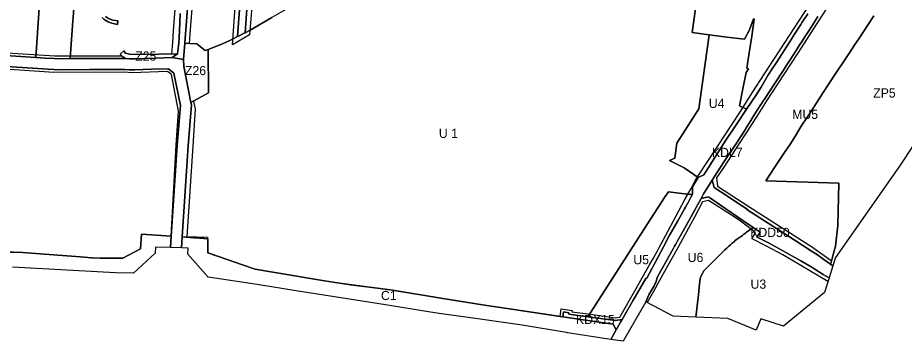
# Model space of a CAD drawing. Extents: x 7428841 to 7433518, y 5545054 to 5546840.
# Drawn here: x 7431956 to 7432924, y 5545054 to 5545407 of the extents above; entities that cross this region are included whole.
import ezdxf

# ---------------------------------------------------------------- set-up
doc = ezdxf.new("R2010")
doc.units = 0
for name, color, linetype in [('linie_rozgraniczajace', 7, 'Continuous'), ('linie_zabudowy_nieprzekraczalne', 7, 'Continuous'), ('oznaczenia_przeznaczen', 7, 'Continuous')]:
    doc.layers.add(name, color=color, linetype=linetype)

msp = doc.modelspace()

# ---------------------------------------------------------------- linework, layer by layer
at = {"layer": 'linie_rozgraniczajace'}
for points in [[(7432196.1, 5545386.25), (7432202.71, 5545474.72), (7432206.08, 5545525.88), (7432208.81, 5545561.69), (7432203.6, 5545569.04), (7432210.29, 5545567.85), (7432216.33, 5545566.52), (7432223.28, 5545565.18), (7432216.71, 5545560.01), (7432214.06, 5545525.32), (7432212.38, 5545499.74), (7432210.69, 5545474.16), (7432207.56, 5545432.32), (7432204.44, 5545390.47), (7432203.54, 5545390.02), (7432197.14, 5545386.77)], [(7432204.44, 5545390.47), (7432207.56, 5545432.32), (7432210.69, 5545474.16), (7432212.38, 5545499.74), (7432214.06, 5545525.32), (7432216.71, 5545560.01), (7432223.28, 5545565.18), (7432244.58, 5545561.06), (7432283.54, 5545552.91), (7432290.42, 5545551.44), (7432291.32, 5545550.69), (7432296.95, 5545543.74), (7432296.3, 5545532.35), (7432295.25, 5545513.02), (7432294.01, 5545489.23), (7432293.34, 5545476.24), (7432291.3, 5545440.58), (7432274.26, 5545430.67), (7432233.45, 5545406.94), (7432209.79, 5545393.18)], [(7432667.52, 5545251.05), (7432673.15, 5545253.66), (7432675.27, 5545270.1), (7432699.59, 5545307.32), (7432710.72, 5545388.26), (7432729.95, 5545385.76), (7432749.18, 5545383.25), (7432754.57, 5545393.55), (7432759.06, 5545405.63), (7432759.96, 5545405.26), (7432757.16, 5545386.62), (7432754.42, 5545368.61), (7432751.84, 5545351.8), (7432753.62, 5545351.19), (7432750.92, 5545347.04), (7432747.88, 5545331.2), (7432743.92, 5545310.59), (7432751.27, 5545307.07), (7432740.14, 5545290.19), (7432729, 5545273.31), (7432704.97, 5545235.65), (7432698.55, 5545232.67), (7432689.21, 5545239.02), (7432683.27, 5545243.05)], [(7432067.99, 5545367.17), (7432072.24, 5545370.55), (7432074.07, 5545368.16), (7432078.32, 5545367.09), (7432089.62, 5545366.59), (7432110.15, 5545367.09), (7432130.68, 5545367.58), (7432125.02, 5545363.36), (7432106.88, 5545362.74), (7432083.68, 5545361.95), (7432078.49, 5545361.82), (7432073.98, 5545362.3), (7432071.11, 5545363.99)], [(7432137.2, 5545361.26), (7432138.7, 5545378.94), (7432143.99, 5545378.66), (7432151.8, 5545378.26), (7432160.95, 5545371.14), (7432163.99, 5545372.31), (7432164.46, 5545325.04), (7432145.38, 5545314.39), (7432137.63, 5545353.68)], [(7432701.88, 5545209.84), (7432704.68, 5545214.94), (7432707.84, 5545219.89), (7432710.99, 5545224.83), (7432714.12, 5545229.84), (7432714.13, 5545229.81), (7432716.08, 5545221.55), (7432731.85, 5545211.37), (7432741.98, 5545204.74), (7432752.11, 5545198.11), (7432751.92, 5545197.81), (7432803.36, 5545164.61), (7432822.42, 5545152.36), (7432828.77, 5545148.28), (7432835.85, 5545143.22), (7432842.93, 5545138.16), (7432845.64, 5545136.22), (7432841.47, 5545123.06), (7432837.72, 5545125.39), (7432835.19, 5545126.96), (7432821.88, 5545135.06), (7432810.56, 5545141.82), (7432794.5, 5545150.78), (7432786.64, 5545155.11), (7432778.78, 5545159.44), (7432775.28, 5545161.37), (7432771.78, 5545163.29), (7432763.89, 5545167.27), (7432762.82, 5545167.63), (7432766.45, 5545172.84), (7432758.66, 5545178.14), (7432747.51, 5545185.75), (7432722.99, 5545202.46), (7432710.96, 5545210.66), (7432709.63, 5545211.57)], [(7432578.18, 5545080.77), (7432642.84, 5545180.91), (7432662.74, 5545211.71), (7432666.18, 5545217.04), (7432689.64, 5545214.06), (7432692.67, 5545214.56), (7432690.37, 5545210.45), (7432687.65, 5545205.38), (7432684.92, 5545200.31), (7432683.84, 5545198.41), (7432680.11, 5545191.89), (7432676.38, 5545185.38), (7432667.04, 5545168.88), (7432660.91, 5545157.16), (7432654.78, 5545145.45), (7432642.58, 5545122.98), (7432641.73, 5545122.61), (7432627.38, 5545098.18), (7432620.55, 5545085.97), (7432615.62, 5545077.57), (7432615.6, 5545077.57), (7432608.55, 5545076.48)], [(7432641.43, 5545096.89), (7432644.83, 5545104.52), (7432648.35, 5545110.71), (7432649.44, 5545112.59), (7432650.53, 5545114.48), (7432651.51, 5545116.26), (7432652.48, 5545118.04), (7432653.05, 5545119.59), (7432654.5, 5545124.17), (7432671.87, 5545155.36), (7432673.03, 5545157.66), (7432674.18, 5545159.95), (7432675.78, 5545162.8), (7432680.53, 5545171.2), (7432685.28, 5545179.6), (7432701.88, 5545209.84), (7432709.63, 5545211.57), (7432710.96, 5545210.66), (7432722.99, 5545202.46), (7432747.51, 5545185.75), (7432758.66, 5545178.14), (7432755.12, 5545175.61), (7432751.57, 5545173.08), (7432750.29, 5545172.03), (7432748.61, 5545170.72), (7432746.93, 5545169.41), (7432743.8, 5545167.12), (7432740.66, 5545164.83), (7432739.24, 5545163.72), (7432737.82, 5545162.61), (7432736.82, 5545161.77), (7432735.83, 5545160.92), (7432733.92, 5545159.23), (7432732.01, 5545157.53), (7432729.98, 5545155.69), (7432727.96, 5545153.85), (7432716.58, 5545142.62), (7432711.01, 5545137.03), (7432707.3, 5545133.23), (7432705.99, 5545131.91), (7432705.1, 5545131.18), (7432704.58, 5545130.49), (7432703.99, 5545129.52), (7432703.61, 5545128.75), (7432702.34, 5545126.11), (7432701.71, 5545124.61), (7432701.08, 5545123.35), (7432700.7, 5545122.73), (7432699.7, 5545112.9), (7432698.88, 5545104.78), (7432696.27, 5545080.44), (7432671.24, 5545081.55)], [(7432696.27, 5545080.44), (7432698.88, 5545104.78), (7432699.7, 5545112.9), (7432700.7, 5545122.73), (7432701.08, 5545123.35), (7432701.71, 5545124.61), (7432702.34, 5545126.11), (7432703.61, 5545128.75), (7432703.99, 5545129.52), (7432704.58, 5545130.49), (7432705.1, 5545131.18), (7432705.99, 5545131.91), (7432707.3, 5545133.23), (7432711.01, 5545137.03), (7432716.58, 5545142.62), (7432727.96, 5545153.85), (7432729.98, 5545155.69), (7432732.01, 5545157.53), (7432733.92, 5545159.23), (7432735.83, 5545160.92), (7432736.82, 5545161.77), (7432737.82, 5545162.61), (7432739.24, 5545163.72), (7432740.66, 5545164.83), (7432743.8, 5545167.12), (7432746.93, 5545169.41), (7432748.61, 5545170.72), (7432750.29, 5545172.03), (7432751.57, 5545173.08), (7432755.12, 5545175.61), (7432758.66, 5545178.14), (7432766.45, 5545172.84), (7432762.82, 5545167.63), (7432763.89, 5545167.27), (7432771.78, 5545163.29), (7432775.28, 5545161.37), (7432778.78, 5545159.44), (7432786.64, 5545155.11), (7432794.5, 5545150.78), (7432810.56, 5545141.82), (7432821.88, 5545135.06), (7432835.19, 5545126.96), (7432837.72, 5545125.39), (7432841.47, 5545123.06), (7432836.5, 5545107.35), (7432791.84, 5545070.54), (7432767.08, 5545078.44), (7432762.15, 5545066.15), (7432731.09, 5545078.89)], [(7432135.09, 5545155.79), (7432135.85, 5545167.75), (7432147.96, 5545166.94), (7432150.43, 5545166.77), (7432163.92, 5545165.87), (7432163.78, 5545150.44), (7432168.06, 5545148.95), (7432200.53, 5545137.62), (7432215.26, 5545132.49), (7432234.5, 5545129.24), (7432291.14, 5545119.99), (7432319.41, 5545115.67), (7432351.95, 5545111.58), (7432365.27, 5545109.89), (7432418.01, 5545101.07), (7432465.59, 5545093.37), (7432490.19, 5545089.57), (7432551.02, 5545080.69), (7432575.82, 5545077.12), (7432605.99, 5545072.61), (7432609.19, 5545066.4), (7432603.31, 5545056.07), (7432598.84, 5545056.76), (7432556.31, 5545063.34), (7432554.98, 5545063.55), (7432506.7, 5545071.44), (7432458.27, 5545078.49), (7432418.71, 5545083.98), (7432406.79, 5545085.63), (7432357.6, 5545093.7), (7432313.43, 5545100.66), (7432262.24, 5545108.71), (7432217.51, 5545115.83), (7432164.31, 5545124.04), (7432142.08, 5545149.06), (7432142.46, 5545155.57)], [(7432551.02, 5545080.69), (7432551.77, 5545086.01), (7432557.71, 5545085.17), (7432557.5, 5545083.69), (7432578.18, 5545080.77), (7432608.55, 5545076.48), (7432615.6, 5545077.57), (7432615.62, 5545077.57), (7432614.49, 5545075.65), (7432612.07, 5545071.62), (7432609.19, 5545066.4), (7432605.99, 5545072.61), (7432575.82, 5545077.12)]]:
    msp.add_lwpolyline(points, close=True, dxfattribs=at)
for points in [[(7431954.01, 5545558.44), (7431956.9, 5545558.72), (7431969.76, 5545559.94), (7431989.12, 5545562.68), (7431986.99, 5545527.39), (7431986.16, 5545515.18), (7431985.24, 5545502.71), (7431966.86, 5545502.19), (7431965.95, 5545492.23), (7431972.63, 5545491.63), (7431979.3, 5545491.02), (7431984.45, 5545490.31), (7431984.46, 5545490.31), (7431981.09, 5545438.88), (7431976.25, 5545363.59), (7431916.07, 5545367.52)], [(7432202.71, 5545474.72), (7432196.1, 5545386.25), (7432190.08, 5545383.2), (7432183.03, 5545379.63), (7432177.88, 5545377.65), (7432163.99, 5545372.31), (7432160.95, 5545371.14), (7432151.8, 5545378.26), (7432143.99, 5545378.66), (7432138.7, 5545378.94), (7432138.74, 5545379.48), (7432142.98, 5545436.66)], [(7432018.14, 5545426.1), (7432016.2, 5545398.51), (7432013.75, 5545362.17), (7432001.79, 5545362.09), (7431996.2, 5545362.19), (7431986.22, 5545362.87), (7431976.25, 5545363.59), (7431981.09, 5545438.88)], [(7432142.98, 5545436.66), (7432138.74, 5545379.48), (7432138.7, 5545378.94), (7432137.2, 5545361.26), (7432125.02, 5545363.36), (7432130.68, 5545367.58), (7432132.02, 5545379.09), (7432132.5, 5545385.71), (7432132.99, 5545392.34), (7432133.27, 5545401.81), (7432133.55, 5545411.29)], [(7432133.55, 5545411.29), (7432133.27, 5545401.81), (7432132.99, 5545392.34), (7432132.5, 5545385.71), (7432132.02, 5545379.09), (7432130.68, 5545367.58), (7432110.15, 5545367.09), (7432089.62, 5545366.59), (7432078.32, 5545367.09), (7432074.07, 5545368.16), (7432072.24, 5545370.55), (7432067.99, 5545367.17), (7432071.11, 5545363.99), (7432073.98, 5545362.3), (7432035.09, 5545362.25), (7432013.75, 5545362.17), (7432016.2, 5545398.51), (7432018.14, 5545426.1)], [(7432697.15, 5545427.52), (7432691.97, 5545390.71), (7432710.72, 5545388.26), (7432699.59, 5545307.32), (7432675.27, 5545270.1), (7432673.15, 5545253.66), (7432667.52, 5545251.05), (7432683.27, 5545243.05), (7432689.21, 5545239.02), (7432698.55, 5545232.67), (7432692.35, 5545222.48), (7432692.67, 5545214.56), (7432689.64, 5545214.06), (7432666.18, 5545217.04), (7432662.74, 5545211.71), (7432642.84, 5545180.91), (7432578.18, 5545080.77), (7432557.5, 5545083.69), (7432557.71, 5545085.17), (7432551.77, 5545086.01), (7432551.02, 5545080.69), (7432490.19, 5545089.57), (7432465.59, 5545093.37), (7432418.01, 5545101.07), (7432365.27, 5545109.89), (7432351.95, 5545111.58), (7432319.41, 5545115.67), (7432291.14, 5545119.99), (7432234.5, 5545129.24), (7432215.26, 5545132.49), (7432200.53, 5545137.62), (7432168.06, 5545148.95), (7432163.78, 5545150.44), (7432163.92, 5545165.87), (7432150.43, 5545166.77), (7432147.96, 5545166.94), (7432135.85, 5545167.75), (7432142.17, 5545267.1), (7432144.02, 5545289.51), (7432145.86, 5545311.93), (7432145.38, 5545314.39), (7432164.46, 5545325.04), (7432163.99, 5545372.31), (7432177.88, 5545377.65), (7432183.03, 5545379.63), (7432190.08, 5545383.2), (7432196.1, 5545386.25), (7432197.14, 5545386.77), (7432203.54, 5545390.02), (7432204.44, 5545390.47), (7432209.79, 5545393.18), (7432233.45, 5545406.94)], [(7432818.19, 5545411.13), (7432812.33, 5545402.01), (7432810.68, 5545399.44), (7432803.17, 5545387.74), (7432800.95, 5545384.33), (7432792.46, 5545371.24), (7432783.97, 5545358.15), (7432779.34, 5545351.02), (7432774.71, 5545343.9), (7432767.45, 5545330.92), (7432761.49, 5545322.12), (7432751.27, 5545307.07), (7432743.92, 5545310.59), (7432747.88, 5545331.2), (7432750.92, 5545347.04), (7432753.62, 5545351.19), (7432751.84, 5545351.8), (7432754.42, 5545368.61), (7432757.16, 5545386.62), (7432759.96, 5545405.26), (7432759.06, 5545405.63), (7432754.57, 5545393.55), (7432749.18, 5545383.25), (7432729.95, 5545385.76), (7432710.72, 5545388.26), (7432691.97, 5545390.71), (7432697.15, 5545427.52)], [(7432829.4, 5545407.97), (7432823.32, 5545398.63), (7432819.27, 5545392.39), (7432815.21, 5545386.15), (7432812.08, 5545381.38), (7432808.94, 5545376.61), (7432805.55, 5545371.01), (7432802.27, 5545365.98), (7432799, 5545360.94), (7432796.85, 5545357.6), (7432794.71, 5545354.26), (7432791.87, 5545349.49), (7432782.83, 5545335.83), (7432775.7, 5545325.12), (7432771.72, 5545319.06), (7432769.37, 5545315.49), (7432768.28, 5545313.77), (7432767.18, 5545312.06), (7432760.67, 5545301.85), (7432756.29, 5545294.73), (7432751.79, 5545287.83), (7432749.06, 5545283.37), (7432740.66, 5545270.01), (7432726.97, 5545250.16), (7432722.97, 5545243.88), (7432718.97, 5545237.6), (7432714.12, 5545229.84), (7432710.99, 5545224.83), (7432707.84, 5545219.89), (7432704.68, 5545214.94), (7432701.88, 5545209.84), (7432685.28, 5545179.6), (7432680.53, 5545171.2), (7432675.78, 5545162.8), (7432674.18, 5545159.95), (7432673.03, 5545157.66), (7432671.87, 5545155.36), (7432654.5, 5545124.17), (7432653.05, 5545119.59), (7432652.48, 5545118.04), (7432651.51, 5545116.26), (7432650.53, 5545114.48), (7432649.44, 5545112.59), (7432648.35, 5545110.71), (7432644.83, 5545104.52), (7432641.43, 5545096.89), (7432618.28, 5545056.6), (7432616.79, 5545054.01), (7432603.31, 5545056.07), (7432609.19, 5545066.4), (7432612.07, 5545071.62), (7432614.49, 5545075.65), (7432615.62, 5545077.57), (7432620.55, 5545085.97), (7432627.38, 5545098.18), (7432641.73, 5545122.61), (7432642.58, 5545122.98), (7432654.78, 5545145.45), (7432660.91, 5545157.16), (7432667.04, 5545168.88), (7432676.38, 5545185.38), (7432680.11, 5545191.89), (7432683.84, 5545198.41), (7432684.92, 5545200.31), (7432687.65, 5545205.38), (7432690.37, 5545210.45), (7432692.67, 5545214.56), (7432692.35, 5545222.48), (7432698.55, 5545232.67), (7432704.97, 5545235.65), (7432729, 5545273.31), (7432740.14, 5545290.19), (7432751.27, 5545307.07), (7432761.49, 5545322.12), (7432767.45, 5545330.92), (7432774.71, 5545343.9), (7432779.34, 5545351.02), (7432783.97, 5545358.15), (7432792.46, 5545371.24), (7432800.95, 5545384.33), (7432803.17, 5545387.74), (7432810.68, 5545399.44), (7432812.33, 5545402.01), (7432818.19, 5545411.13)], [(7432048.59, 5545407.18), (7432050.46, 5545405.31), (7432052.41, 5545403.84), (7432053.08, 5545403.42), (7432055.07, 5545402.41), (7432057.51, 5545401.2), (7432062.08, 5545400.03), (7432065.23, 5545399.37), (7432065.69, 5545403.42), (7432060.01, 5545404.05), (7432055.4, 5545405.97), (7432052.26, 5545408.11)], [(7432052.26, 5545408.11), (7432055.4, 5545405.97), (7432060.01, 5545404.05), (7432065.69, 5545403.42), (7432065.23, 5545399.37), (7432062.08, 5545400.03), (7432057.51, 5545401.2), (7432055.07, 5545402.41), (7432053.08, 5545403.42), (7432052.41, 5545403.84), (7432050.46, 5545405.31), (7432048.59, 5545407.18)], [(7432890.49, 5545408.89), (7432884.23, 5545399.51), (7432873.91, 5545383.89), (7432869.73, 5545377.64), (7432863.64, 5545368.51), (7432857.21, 5545358.81), (7432848.88, 5545346.23), (7432840.54, 5545333.65), (7432835.01, 5545325.11), (7432829.89, 5545317.19), (7432824.77, 5545309.27), (7432817.95, 5545298.91), (7432811.13, 5545288.55), (7432804.71, 5545278.02), (7432798.68, 5545268.13), (7432794.5, 5545261.94), (7432782, 5545243.38), (7432772.49, 5545229.09), (7432772.99, 5545229.07), (7432852.04, 5545226.3), (7432851.12, 5545180.21), (7432848.37, 5545157.54), (7432846.01, 5545148.73), (7432843.65, 5545139.92), (7432842.93, 5545138.16), (7432835.85, 5545143.22), (7432828.77, 5545148.28), (7432822.42, 5545152.36), (7432803.36, 5545164.61), (7432751.92, 5545197.81), (7432752.11, 5545198.11), (7432741.98, 5545204.74), (7432731.85, 5545211.37), (7432716.08, 5545221.55), (7432714.13, 5545229.81), (7432714.12, 5545229.84), (7432718.97, 5545237.6), (7432722.97, 5545243.88), (7432726.97, 5545250.16), (7432740.66, 5545270.01), (7432749.06, 5545283.37), (7432751.79, 5545287.83), (7432756.29, 5545294.73), (7432760.67, 5545301.85), (7432767.18, 5545312.06), (7432768.28, 5545313.77), (7432769.37, 5545315.49), (7432771.72, 5545319.06), (7432775.7, 5545325.12), (7432782.83, 5545335.83), (7432791.87, 5545349.49), (7432794.71, 5545354.26), (7432796.85, 5545357.6), (7432799, 5545360.94), (7432802.27, 5545365.98), (7432805.55, 5545371.01), (7432808.94, 5545376.61), (7432812.08, 5545381.38), (7432815.21, 5545386.15), (7432819.27, 5545392.39), (7432823.32, 5545398.63), (7432829.4, 5545407.97)], [(7433024.89, 5545405.88), (7432918.2, 5545244.76), (7432848.54, 5545145.38), (7432845.64, 5545136.22), (7432842.93, 5545138.16), (7432843.65, 5545139.92), (7432846.01, 5545148.73), (7432848.37, 5545157.54), (7432851.12, 5545180.21), (7432852.04, 5545226.3), (7432772.99, 5545229.07), (7432772.49, 5545229.09), (7432782, 5545243.38), (7432794.5, 5545261.94), (7432798.68, 5545268.13), (7432804.71, 5545278.02), (7432811.13, 5545288.55), (7432817.95, 5545298.91), (7432824.77, 5545309.27), (7432829.89, 5545317.19), (7432835.01, 5545325.11), (7432840.54, 5545333.65), (7432848.88, 5545346.23), (7432857.21, 5545358.81), (7432863.64, 5545368.51), (7432869.73, 5545377.64), (7432873.91, 5545383.89), (7432884.23, 5545399.51), (7432890.49, 5545408.89)], [(7431916.07, 5545367.52), (7431976.25, 5545363.59), (7431986.22, 5545362.87), (7431996.2, 5545362.19), (7432001.79, 5545362.09), (7432013.75, 5545362.17), (7432035.09, 5545362.25), (7432073.98, 5545362.3), (7432078.49, 5545361.82), (7432083.68, 5545361.95), (7432106.88, 5545362.74), (7432125.02, 5545363.36), (7432137.2, 5545361.26), (7432137.63, 5545353.68), (7432145.38, 5545314.39), (7432145.86, 5545311.93), (7432144.02, 5545289.51), (7432142.17, 5545267.1), (7432135.85, 5545167.75), (7432135.09, 5545155.79), (7432123.09, 5545156.15), (7432123.88, 5545168.56), (7432130.21, 5545267.97), (7432133.04, 5545302.46), (7432133.77, 5545311.25), (7432126.83, 5545346.41), (7432120.79, 5545351.21), (7432102.41, 5545350.58), (7432084.03, 5545349.95), (7432078.01, 5545349.81), (7432073.35, 5545350.3), (7432035.13, 5545350.25), (7432001.7, 5545350.09), (7431995.69, 5545350.2), (7431989.5, 5545350.62), (7431915.28, 5545355.55)], [(7431915.28, 5545355.55), (7431989.5, 5545350.62), (7431995.69, 5545350.2), (7432001.7, 5545350.09), (7432035.13, 5545350.25), (7432073.35, 5545350.3), (7432078.01, 5545349.81), (7432084.03, 5545349.95), (7432102.41, 5545350.58), (7432120.79, 5545351.21), (7432126.83, 5545346.41), (7432133.77, 5545311.25), (7432133.04, 5545302.46), (7432130.21, 5545267.97), (7432123.88, 5545168.56), (7432091.35, 5545170.74), (7432090.47, 5545154.75), (7432070.92, 5545144.6), (7432046.18, 5545144.47), (7432037.48, 5545145.11), (7432036.99, 5545145.15), (7432024.81, 5545146.06), (7432009.78, 5545147.16), (7431980.91, 5545149.31), (7431971.46, 5545150.01), (7431962.01, 5545150.71), (7431942, 5545151.39)], [(7431942, 5545151.39), (7431962.01, 5545150.71), (7431971.46, 5545150.01), (7431980.91, 5545149.31), (7432009.78, 5545147.16), (7432024.81, 5545146.06), (7432036.99, 5545145.15), (7432037.48, 5545145.11), (7432046.18, 5545144.47), (7432070.92, 5545144.6), (7432090.47, 5545154.75), (7432091.35, 5545170.74), (7432123.88, 5545168.56), (7432123.09, 5545156.15), (7432106.54, 5545156.64), (7432106.39, 5545150.16), (7432082.79, 5545128.3), (7432062.86, 5545128.67), (7432016.49, 5545131.23), (7431950.63, 5545134.86)]]:
    msp.add_lwpolyline(points, dxfattribs=at)
at = {"layer": 'linie_zabudowy_nieprzekraczalne'}
for points in [[(7432153.54, 5545603.66), (7432154.37, 5545569.23), (7432154.56, 5545548.02), (7432154.6, 5545528.65), (7432153.03, 5545503.9), (7432151.29, 5545480.41), (7432144.29, 5545389.36), (7432143.72, 5545383.25), (7432143.33, 5545378.72)], [(7432223.73, 5545560.44), (7432221, 5545558.27), (7432220.04, 5545544.59), (7432217.35, 5545499.4), (7432212.89, 5545431.96), (7432209.35, 5545388.08), (7432190.54, 5545377.1), (7432197.72, 5545475.06), (7432203.3, 5545562.75), (7432199.08, 5545569.34)], [(7432613.18, 5545080.26), (7432629.5, 5545108.9), (7432645.5, 5545137.17), (7432650.14, 5545144.69), (7432660.47, 5545164.33), (7432677.75, 5545196.19), (7432684.65, 5545209.15), (7432690.98, 5545220.65), (7432696.69, 5545231.27), (7432711.59, 5545253.6), (7432744.32, 5545303.58), (7432758.27, 5545326.12), (7432771.21, 5545345.61), (7432820.13, 5545421.04), (7432835.52, 5545445.02), (7432843.74, 5545457.64)], [(7432868.11, 5545464.09), (7432861.59, 5545452.76), (7432839.5, 5545418.06), (7432834.55, 5545410.53), (7432807.19, 5545367.66), (7432785.78, 5545335.05), (7432773.39, 5545316.35), (7432764.17, 5545301.67), (7432752.49, 5545283.47), (7432742.82, 5545268.39), (7432726.52, 5545243.78), (7432718.77, 5545232.19), (7432718.77, 5545232.19)], [(7432124.52, 5545367.61), (7432125.47, 5545379.64), (7432126.39, 5545392.38), (7432127.84, 5545411.5), (7432129.84, 5545436.97), (7432130.03, 5545439.28)], [(7431772.52, 5545365.39), (7431805.61, 5545372.08), (7431812.34, 5545373.31), (7431820.95, 5545374.43), (7431827.8, 5545375.02), (7431842.35, 5545375.33), (7431886.18, 5545372.51), (7431956.49, 5545367.85), (7431996.97, 5545365.16)], [(7431996.97, 5545365.16), (7432069.8, 5545365.28)], [(7432123.94, 5545168.43), (7432129.29, 5545267.88), (7432131.88, 5545305.09), (7432124.1, 5545344.75), (7432119.78, 5545348.17), (7432080.99, 5545346.88), (7432073.28, 5545347.3), (7431995.59, 5545347.2), (7431915.08, 5545352.55), (7431843.14, 5545357.32), (7431836.54, 5545357.33), (7431828.92, 5545357.05), (7431819.33, 5545356.19), (7431810.9, 5545354.8)], [(7432148.17, 5545315.73), (7432150.11, 5545307.16), (7432147.25, 5545266.67), (7432140.86, 5545168.33)], [(7432718.77, 5545232.25), (7432719.65, 5545223.06), (7432753.83, 5545200.88), (7432824.56, 5545155.74)], [(7432703.55, 5545206.11), (7432694.53, 5545189.51), (7432677.3, 5545157.28), (7432658.86, 5545124.09), (7432649.8, 5545108.13), (7432643.13, 5545096.11)], [(7432756.4, 5545176.14), (7432753.98, 5545177.97), (7432743.42, 5545186.19), (7432735.21, 5545191.57), (7432710.02, 5545207.56), (7432703.55, 5545206.11)], [(7431514.11, 5545172.58), (7431532.68, 5545171.33), (7431569.2, 5545169.3), (7431638.61, 5545165.58), (7431752.44, 5545159.69), (7431763.58, 5545159.17), (7431764.56, 5545178.47), (7431808.88, 5545176.74), (7431807.66, 5545157.3), (7431882.24, 5545153.07), (7431962.01, 5545150.71), (7432046.18, 5545144.47), (7432058.55, 5545144.53), (7432070.92, 5545144.6), (7432090.47, 5545154.75), (7432091.35, 5545170.74), (7432123.82, 5545168.62)], [(7432140.86, 5545168.33), (7432163.28, 5545167.4), (7432163.78, 5545150.44), (7432215.26, 5545132.49), (7432291.14, 5545119.99), (7432362.02, 5545110.3), (7432418.01, 5545101.07), (7432490.19, 5545089.57), (7432548.05, 5545081.11), (7432548.05, 5545081.11)], [(7432757.41, 5545165.82), (7432761.26, 5545172.4), (7432756.4, 5545176.14)], [(7432840.25, 5545119.09), (7432790.93, 5545148.12), (7432773.41, 5545157.83), (7432757.43, 5545165.87)], [(7432824.56, 5545155.74), (7432824.75, 5545155.61)], [(7432824.75, 5545155.61), (7432843.95, 5545142.19)], [(7432548.17, 5545081.1), (7432549.23, 5545089.4), (7432561.11, 5545087.72), (7432560.9, 5545086.24), (7432578.6, 5545083.74), (7432608.53, 5545079.52), (7432613.18, 5545080.26)]]:
    msp.add_lwpolyline(points, dxfattribs=at)

# ---------------------------------------------------------------- texts
at = {"layer": 'oznaczenia_przeznaczen'}
for s, p in [('Z25', (7432084.58, 5545360.01)), ('Z26', (7432138.82, 5545344.22)), ('ZP5', (7432889.66, 5545319.75)), ('U4', (7432710.26, 5545308.37)), ('MU5', (7432801.28, 5545296.43)), ('U 1', (7432415.83, 5545275.69)), ('KDL7', (7432713.67, 5545254.96)), ('KDD50', (7432755.46, 5545167.72)), ('U6', (7432687.28, 5545140.39)), ('U5', (7432627.98, 5545137.95)), ('U3', (7432755.82, 5545111.28)), ('C1', (7432352.66, 5545098.91)), ('KDX15', (7432565.37, 5545072.79))]:
    msp.add_text(s, height=10, dxfattribs=at).set_placement(p)

doc.saveas('drawing.dxf')
